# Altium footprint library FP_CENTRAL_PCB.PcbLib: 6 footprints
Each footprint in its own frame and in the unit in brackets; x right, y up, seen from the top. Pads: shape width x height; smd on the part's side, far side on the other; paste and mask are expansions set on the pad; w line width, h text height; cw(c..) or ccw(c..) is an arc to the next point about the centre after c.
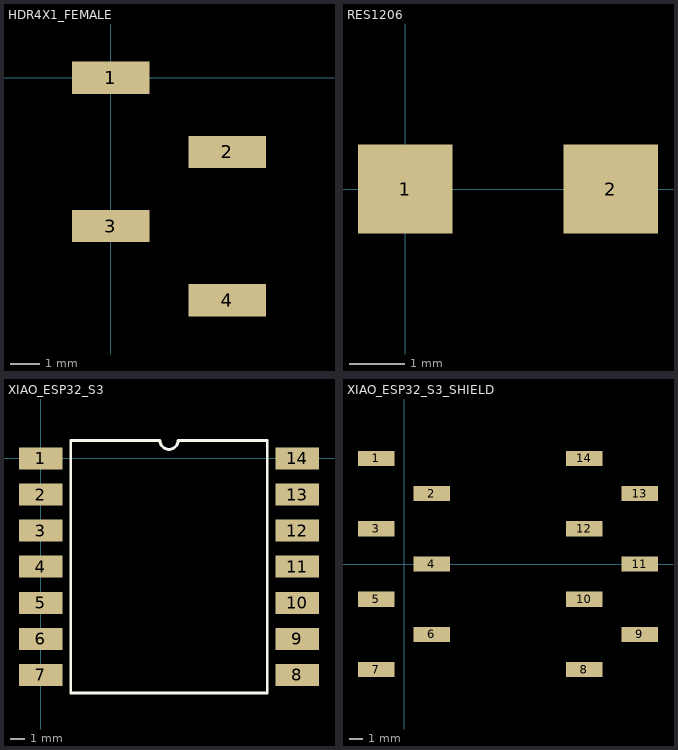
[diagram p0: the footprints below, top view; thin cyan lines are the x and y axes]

## HDR4X1_FEMALE [mm]
pads (4):
  rect 2.65x1.1 smd: 1(0,0) 2(4,-2.54) 3(0,-5.08) 4(4,-7.62)
3D body "2MM-SMD-PIN-HEADER-FEMALE.STEP": height 2.33, standoff 0.01, extent -0.762,-7.703 4.738,0.337

## PCBComponent_1 [mm]

## PCBComponent_1 - duplicate [mm]

## RES1206 [mm]
pads (2):
  rect 1.7x1.6 smd: 1(0,0) 2(3.7,0)
3D body "RC1206.stp": height 0.55, standoff 0, extent 0.253,-0.787 3.353,0.813

## XIAO_ESP32_S3 [mm]
pads (14):
  rect 3x1.52 smd: 1(0,0) 2(0,-2.5) 3(0,-5) 4(0,-7.5) 5(0,-10) 6(0,-12.5) 7(0,-15) 8(17.78,-15) 9(17.78,-12.5) 10(17.78,-10) 11(17.78,-7.5) 12(17.78,-5) 13(17.78,-2.5) 14(17.78,0)
Top Overlay:
  lines w0.2: 2.085,-16.25 15.695,-16.25 15.695,1.25 9.515,1.25 cw(c8.89,1.25) 8.265,1.25 2.085,1.25 2.085,-16.25
3D body "Seeed Studio XIAO-ESP32-S3-Sense_ALONE.STEP": height 4.47, standoff 0.01, extent -0.015,-17.995 17.765,4.487

## XIAO_ESP32_S3_SHIELD [mm]
pads (14):
  rect 2.65x1.1 smd: 1(-2,7.62) 2(2,5.08) 3(-2,2.54) 4(2,0) 5(-2,-2.54) 6(2,-5.08) 7(-2,-7.62) 8(13,-7.62) 9(17,-5.08) 10(13,-2.54) 11(17,0) 12(13,2.54) 13(17,5.08) 14(13,7.62)
3D body "2MM-SMD-PIN-HEADER-FEMALE.STEP": height 2.33, standoff 0.01, extent 12.238,-0.083 17.738,7.957
3D body "2MM-SMD-PIN-HEADER-FEMALE.STEP": height 2.33, standoff 0.01, extent 12.238,-5.163 17.738,2.877
3D body "2MM-SMD-PIN-HEADER-FEMALE.STEP": height 2.33, standoff 0.01, extent -2.762,-5.163 2.738,2.877
3D body "2MM-SMD-PIN-HEADER-FEMALE.STEP": height 2.33, standoff 0.01, extent -2.762,-0.083 2.738,7.957
3D body "Seeed Studio XIAO-ESP32-S3-Sense_ALONE.STEP": height 7.21, standoff 2.75, extent -1.401,-10.773 16.379,11.709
